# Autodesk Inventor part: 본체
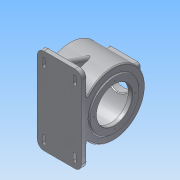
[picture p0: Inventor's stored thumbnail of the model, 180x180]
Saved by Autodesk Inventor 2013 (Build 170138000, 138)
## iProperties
Created: 2015-06
Part Number: 본체
Material: 알루미늄 6061
Document SubType Name: Modeling
Designer: ST
Density: 2.71 g/cm^3
Mass: 3274.09 g
Surface Area: 2302.99 cm^2
Volume: 1208.15 cm^3
Author: ST
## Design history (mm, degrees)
sketch "스케치1"
  geometry: L1 (0, 0)-(134, 0); L2 (0, 0)-(0, 65); L3 (0, 65)-(13, 65); L4 (13, 65)-(13, 85); L5 (13, 85)-(131, 85); L6 (131, 85)-(131, 65); L7 (131, 65)-(134, 65); L8 (7.5, 0)-(7.5, 15); L9 (7.5, 15)-(10.5, 15); L10 (10.5, 15)-(10.5, 23.5); L11 (10.5, 23.5)-(24.5, 23.5); L12 (24.5, 23.5)-(24.5, 29.368); L13 (24.5, 29.368)-(21, 31); L14 (21, 31)-(21, 77); L15 (21, 77)-(123, 77); L16 (123, 77)-(123, 47.5); L17 (123, 47.5)-(134, 47.5); L18 (134, 47.5)-(134, 65)
  constraints: 36 end point, 9 parallel, 5 perpendicular, 1 collinear, 1 horizontal, 1 point on line
  dimensions: "d5" = 134 distance of L1.start L1.end; "d7" = 170 diameter of L5 L1; "d8" = 130 diameter of L3 L1; "d9" = 30 diameter of L9 L1; "d10" = 47 diameter of L11 L1; "d11" = 62 diameter of L13.end L1; "d14" = 8 distance between parallel lines of L14 L4; "d16" = 130 diameter of L7 L1; "d17" = 8 distance between parallel lines of L16 L6; "d18" = 102 distance between parallel lines of L14 L16; "d19" = 134 distance between parallel lines of L18 L2; "d20" = 95 diameter of L17 L1; "d21" = 154 diameter of L15 L1; "d23" = 3 distance between parallel lines of L8 L10; "d24" = 115 deg angle of L14 L13; "d25" = 13 distance of L2.end L3.end; "d26" = 3.5 distance between parallel lines of L14 L12; "d27" = 14 distance between parallel lines of L12 L10
revolve "회전1" sketch "스케치1" stored, may be unused: angle "d28" = 90 deg
node "작업 평면1"
sketch "스케치2"
  geometry: L1 (59, 115)-(-59, 115); L2 (-59, 115)-(-59, -115); L3 (-59, -115)-(59, -115); L4 (59, 115)-(59, -115); 1 further point
  constraints: 8 end point, 2 perpendicular, 1 horizontal, 1 parallel
  dimensions: "d29" = 230 distance of L3.end L1.start; "d31" = 115 distance from line of L1 point (72, 0); "d33" = 118 distance of L1.start L1.end; "d34" = 13 distance from line of point (72, 0) L4
extrude "돌출1" join sketch "스케치2" distance "d35" = 14; taper "d36" = 0 deg
sketch "스케치3"
  geometry: L1 (0, 0)-(134.437, 0); L2 (0, -65)-(0, 65) reference; L3 (0, -65)-(0, 65) reference; L4 (0, 65)-(13, 65) reference; L5 (13, 65)-(13, 85) reference; L6 (13, 85)-(131, 85) reference; L7 (131, 85)-(131, 65) reference; L8 (131, 65)-(134, 65) reference; L9 (134, 65)-(134, 47.5) reference; L10 (134, 47.5)-(123, 47.5) reference; L11 (123, 47.5)-(123, 77) reference; L12 (123, 77)-(21, 77) reference; L13 (21, 77)-(21, 31) reference; L14 (21, 31)-(24.5, 29.368) reference; L15 (24.5, 29.368)-(24.5, 23.5) reference; L16 (24.5, 23.5)-(10.5, 23.5) reference; L17 (10.5, 23.5)-(10.5, 15) reference; L18 (10.5, 15)-(7.5, 15) reference; L19 (7.5, 15)-(7.5, -15) reference; L20 (7.5, -15)-(10.5, -15) reference; L21 (10.5, -15)-(10.5, -23.5) reference; L22 (10.5, -23.5)-(24.5, -23.5) reference; L23 (24.5, -23.5)-(24.5, -29.368) reference; L24 (24.5, -29.368)-(21, -31) reference; L25 (21, -31)-(21, -71) reference; L26 (21, -71)-(123, -71) reference; L27 (123, -71)-(123, -47.5) reference; L28 (123, -47.5)-(134, -47.5) reference; L29 (134, -47.5)-(134, -65) reference; L30 (134, -65)-(131, -65) reference; L31 (131, -65)-(131, -85) reference; L32 (131, -85)-(13, -85) reference; L33 (13, -85)-(13, -65) reference; L34 (13, -65)-(0, -65) reference; L35 (123, 47.5)-(21, 47.5); L36 (21, -71)-(21, 77) reference
  constraints: 4 end point, 2 perpendicular, 1 point on line
revolve "회전2" sketch "스케치3" stored, may be unused: angle "d37" = 90 deg
fillet "모깎기1" dims "d38" = 18
sketch "스케치4"
  geometry: L1 (-50, -81)-(-50, -97); L2 (-32, -97)-(-32, -81); A1 r 18 centre (-41, 97) between (-41, 115) and (-59, 97) reference; A2 r 18 centre (41, 97) between (59, 97) and (41, 115) reference; A3 r 18 centre (-41, -97) between (-59, -97) and (-41, -115) reference; A4 r 18 centre (41, -97) between (41, -115) and (59, -97) reference; A5 r 9 centre (-41, -97) between (-50, -97) and (-32, -97); A6 r 9 centre (-41, -81) between (-32, -81) and (-50, -81); 1 further point
  constraints: 4 end point, 4 point on circle, 3 tangent, 2 centre point, 1 coincident, 1 parallel, 1 vertical, 1 vertical alignment
  dimensions: "d41" = 18 distance between parallel lines of L2 L1; "d42" = 16 distance of A5.centre A6.centre
extrude "돌출2" join sketch "스케치4" distance "d43" = 3; taper "d44" = 0 deg
sketch "스케치5"
  geometry: L1 (-50, -81)-(-50, -97) reference; L2 (-32, -97)-(-32, -81) reference; L3 (-37, -81)-(-37, -97); L4 (-45, -97)-(-45, -81); A1 r 9 centre (-41, -97) between (-50, -97) and (-32, -97) reference; A2 r 9 centre (-41, -81) between (-32, -81) and (-50, -81) reference; A3 r 4 centre (-41, -97) between (-45, -97) and (-37, -97); A4 r 4 centre (-41, -81) between (-37, -81) and (-45, -81)
  constraints: 4 end point, 4 point on circle, 2 centre point, 3 other
  dimensions: "d45" = 8 distance between parallel lines of L3 L4
extrude "돌출3" cut sketch "스케치5" stored distance "d47" = 3; taper "d48" = 0 deg
node "작업 평면2"
node "작업 평면3"
sketch "스케치6"
  geometry: L1 (-42.5, 42.5)-(42.5, 42.5); L2 (42.5, 42.5)-(42.5, -42.5); L3 (42.5, -42.5)-(-42.5, -42.5); L4 (-42.5, -42.5)-(-42.5, 42.5); L5 (59, -85)-(59, 85) reference; 4 further points
  constraints: 8 end point, 2 midpoint, 2 parallel, 1 horizontal, 1 horizontal alignment, 1 perpendicular
  dimensions: "d50" = 85 distance of L3.end L1.start; "d52" = 85 distance of L1.start L1.end; "d53" = 16.5 distance between parallel lines of L5 L2
extrude "돌출4" join sketch "스케치6" stored distance "d54" = 3; taper "d55" = 0 deg
sketch "스케치7"
  geometry: L1 (-42.5, -42.5)-(42.5, -42.5) reference; L2 (42.5, -42.5)-(42.5, 42.5) reference; L3 (42.5, 42.5)-(-42.5, 42.5) reference; L4 (-42.5, 42.5)-(-42.5, -42.5) reference; L5 (-42.5, 42.5)-(-42.5, -42.5) reference; L6 (-42.5, 0)-(42.5, 0); C1 r 35 at (0, 0)
  constraints: 3 midpoint, 2 end point, 1 centre point
  dimensions: "d56" = 70 diameter of C1
extrude "돌출5" cut sketch "스케치7" stored distance "d58" = 3; taper "d59" = 0 deg
fillet "모깎기2" dims "d60" = 7
sketch "스케치8"
  geometry: A1 r 7 centre (-35.5, 35.5) between (-35.5, 42.5) and (-42.5, 35.5) reference; A2 r 7 centre (35.5, 35.5) between (42.5, 35.5) and (35.5, 42.5) reference; A3 r 7 centre (35.5, -35.5) between (35.5, -42.5) and (42.5, -35.5) reference; A4 r 7 centre (-35.5, -35.5) between (-42.5, -35.5) and (-35.5, -42.5) reference; 4 further points
  constraints: 4 coincident
hole "구멍1" sketch "스케치8" at (-35.5, 35.5), (35.5, 35.5), (35.5, -35.5), (-35.5, -35.5) diameter "d61" = 3.242; stored, may be unused: countersink angle "d65" = 90 deg, drill point angle "d67" = 118 deg; dims "d62" = 10, "d63" = 4, "d64" = 2, "d66" = 13
sketch "스케치9"
  geometry: L1 (-115, -71)-(-46.733, -71) reference; L2 (-42.5, 73.612)-(-42.5, 88) reference; L3 (-42.5, 88)-(-35, 88) reference; L4 (-35, 88)-(-35, 68.586) reference; L5 (35, 68.586)-(35, 88) reference; L6 (35, 88)-(42.5, 88) reference; L7 (42.5, 88)-(42.5, 73.612) reference; L8 (46.733, -71)-(115, -71) reference; L9 (115, -71)-(115, -85) reference; L10 (115, -85)-(-115, -85) reference; L11 (-115, -85)-(-115, -71) reference; L12 (84.87, -4.703)-(109, -71); L13 (97, -71)-(115, -71) reference; A1 r 85 centre (0, 0) between (-42.5, 73.612) and (-46.733, -71) reference; A2 r 77 centre (0, 0) between (-35, 68.586) and (35, 68.586) reference; A3 r 85 centre (0, 0) between (46.733, -71) and (42.5, 73.612) reference; A4 r 85 centre (0, 0) between (46.733, -71) and (-46.733, -71) reference
  constraints: 2 end point, 2 point on circle, 1 point on line
  dimensions: "d68" = 6 distance from line of L9 L12.end; "d70" = 110 deg angle of L8 L12
extrude "돌출6" join sketch "스케치9" stored distance "d71" = 15; taper "d72" = 0 deg
fillet "모깎기3" dims "d73" = 7.5
node "작업 평면5"
  node "작업 평면4"
sketch "스케치10"
  geometry: L1 (101.5, 23.206)-(101.5, -145.892) reference; 3 further points
  constraints: 1 horizontal alignment, 1 midpoint, 1 other
  dimensions: "d76" = 59 distance of point (101.5, -61.343) point (42.5, -61.343)
feature "엠보싱1" sketch "스케치10" dims "d78" = 0.5, "d79" = 0
fillet "모깎기4" dims "d80" = 0.3
chamfer "모따기1" distance "d81" = 1; stored, may be unused: second distance "d82" = 2, angle "d83" = 45 deg
fillet "모깎기5" dims "d84" = 3
fillet "모깎기6" dims "d85" = 3
sketch "스케치11"
  geometry: C1 r 65 at (0, 0) reference; 1 further point
  constraints: 1 vertical alignment
  dimensions: "d86" = 55 distance of C1.centre point (0, 55)
hole "구멍2" sketch "스케치11" at (0, 55) diameter "d87" = 3.242; stored, may be unused: countersink angle "d91" = 90 deg, drill point angle "d93" = 118 deg; dims "d88" = 10, "d89" = 4, "d90" = 2, "d92" = 13
fillet "모깎기7" dims "d97" = 3
chamfer "모따기2" distance "d98" = 1; stored, may be unused: second distance "d99" = 2, angle "d100" = 45 deg
fillet "모깎기8" dims "d101" = 3
node "솔리드1"
mirror "대칭1"
mirror "대칭2"
mirror "대칭3"
pattern_circular "원형 패턴1" dims angle "d95" = 360 deg
node "투영된 루프1"
node "투영된 루프2"
node "절단 모서리 투영1"
node "절단 모서리 투영2"
other parameters: "d49" = -173, "d74" = -25 deg
